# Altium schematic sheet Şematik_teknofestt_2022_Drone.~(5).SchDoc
size A4; SheetNumber: 1; SheetTotal: 1
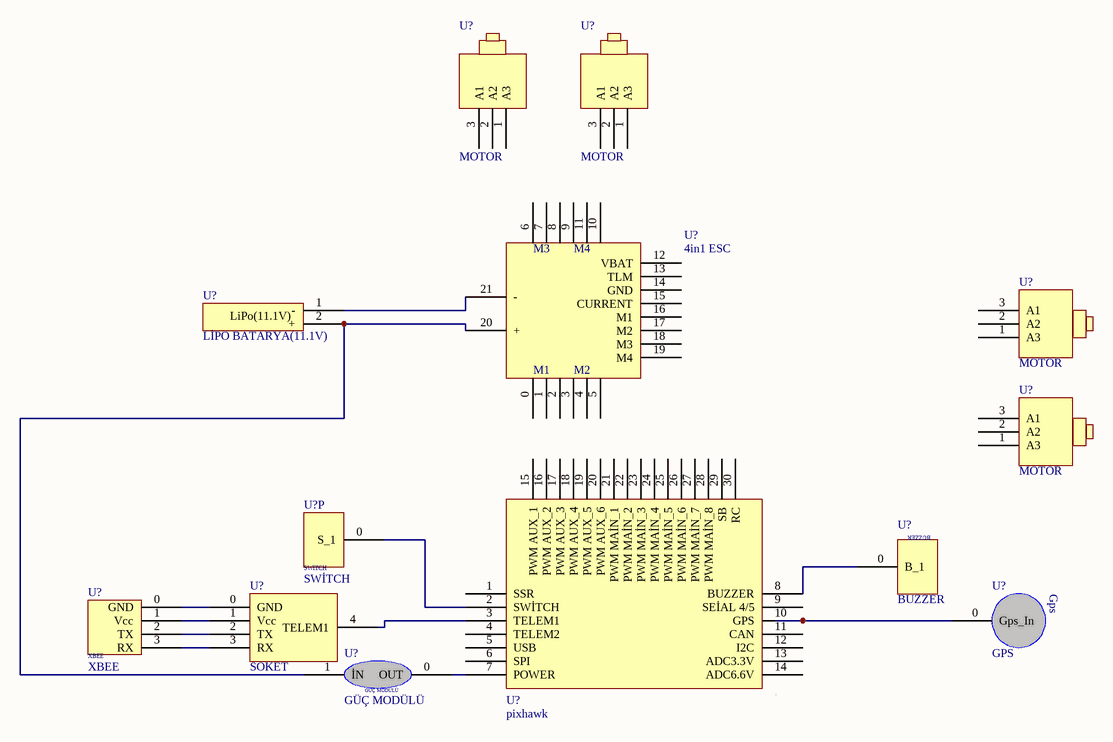
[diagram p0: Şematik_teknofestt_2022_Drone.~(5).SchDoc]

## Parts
(Parts that share a designator on the sheet are numbered #1, #2 ... from top to bottom, then left to right.)
U?#1  pixhawk
U?#2  MOTOR
U?#3  MOTOR
U?#4  4in1 ESC
U?#5  LİPO BATARYA(11.1V)
U?#6  MOTOR
U?#7  MOTOR
U?#8  BUZZER
U?#9  GPS
U?#10  XBEE
U?#11  SOKET
U?#12  GÜÇ MODÜLÜ
U?P  SWİTCH

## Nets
NetU?#1_2: U?#1.2(SWİTCH) U?P.0(S_1)
NetU?#1_3: U?#1.3(TELEM1) U?#11.4(TELEM1)
NetU?#1_7: U?#1.7(POWER) U?#12.0(OUT)
NetU?#1_8: U?#1.8(BUZZER) U?#8.0(B_1)
NetU?#1_10: U?#1.10(GPS) U?#9.0(Gps_In)
NetU?#4_20: U?#4.20(+) U?#5.2(+) U?#12.1(İN)
NetU?#4_21: U?#4.21(-) U?#5.1(-)
NetU?#10_0: U?#10.0(GND) U?#11.0(GND)
NetU?#10_1: U?#10.1(Vcc) U?#11.1(Vcc)
NetU?#10_2: U?#10.2(TX) U?#11.2(TX)
NetU?#10_3: U?#10.3(RX) U?#11.3(RX)

Not connected (* = marked no-connect by the designer): U?#1 1(SSR) 4(TELEM2) 5(USB) 6(SPI) 9(SEİAL_4/5) 11(CAN) 12(I2C) 13(ADC3.3V) 14(ADC6.6V) 15(PWM_AUX_1) 16(PWM_AUX_2) 17(PWM_AUX_3) 18(PWM_AUX_4) 19(PWM_AUX_5) 20(PWM_AUX_6) 21(PWM_MAİN_1) 22(PWM_MAİN_2) 23(PWM_MAİN_3) 24(PWM_MAİN_4) 25(PWM_MAİN_5) 26(PWM_MAİN_6) 27(PWM_MAİN_7) 28(PWM_MAİN_8) 29(SB) 30(RC); U?#2 1(A3) 2(A2) 3(A1); U?#3 1(A3) 2(A2) 3(A1); U?#4 0 1 2 3 4 5 6 7 8 9 10 11 12(VBAT) 13(TLM) 14(GND) 15(CURRENT) 16(M1) 17(M2) 18(M3) 19(M4); U?#6 1(A3) 2(A2) 3(A1); U?#7 1(A3) 2(A2) 3(A1)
